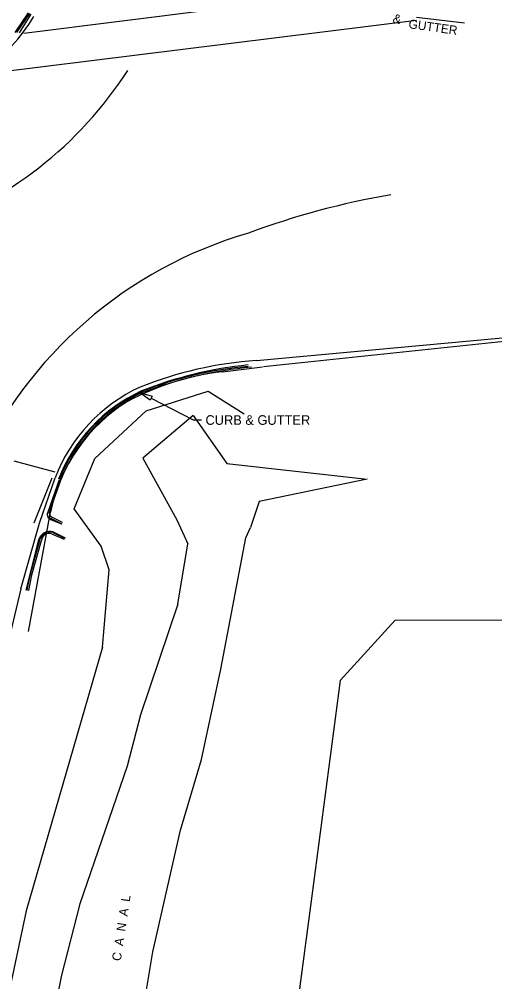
# Model space of a CAD drawing. Extents: x 925226 to 926411, y 852913 to 858733.
# Drawn here: x 925877.3 to 926026.1, y 857833.9 to 858134.9 of the extents above; entities that cross this region are included whole.
import ezdxf

# ---------------------------------------------------------------- set-up
doc = ezdxf.new("R2010")
doc.units = 0
for name, color, linetype in [('BankMent_ep', 7, 'Continuous'), ('CGep_ep', 7, 'Continuous'), ('CGFace_ep', 7, 'Continuous'), ('EndTreat_ep', 7, 'Continuous'), ('Fence_ep', 7, 'Continuous'), ('GuardrailRt_ep', 7, 'Continuous'), ('LaneLine_ep', 7, 'Continuous'), ('PavtAsphalt_ep', 7, 'Continuous'), ('TextLabel', 7, 'Continuous'), ('WaterEdge_ep', 7, 'Continuous'), ('XSPt_ep', 7, 'Continuous')]:
    doc.layers.add(name, color=color, linetype=linetype)

msp = doc.modelspace()

# ---------------------------------------------------------------- linework, layer by layer
at = {"layer": 'BankMent_ep'}
for p, q in [((925916.99, 858012.42), (925936.36, 858018.57)), ((925936.36, 858018.57), (925947.68, 858011.51)), ((925900.92, 857997.55), (925916.99, 858012.42)), ((925894.48, 857981.83), (925900.92, 857997.55)), ((925902.95, 857970.08), (925894.48, 857981.83)), ((925905.41, 857962.71), (925902.95, 857970.08)), ((925903.38, 857938.47), (925905.41, 857962.71)), ((925903.38, 857938.47), (925879.41, 857856.06)), ((925879.41, 857856.06), (925859.54, 857762.3))]:
    msp.add_line(p, q, dxfattribs=at)
at = {"layer": 'CGep_ep'}
for p, q in [((925880.88, 858136.47), (925877.28, 858130.67)), ((925887.16, 857978.4), (925886.13, 857979.3)), ((925890.66, 857976.98), (925887.16, 857978.4)), ((925879.41, 857956.31), (925883.44, 857972.21)), ((925887.93, 857974.56), (925891.68, 857972.76))]:
    msp.add_line(p, q, dxfattribs=at)
for centre, major_axis, ratio, start_param, end_param in [((925960.87, 857905.27), (-120.52, -23.58), 0.994162, 4.617452, 4.898036), ((925936.77, 857972.59), (-47.11, -18.8), 0.999852, 4.763609, 5.531038), ((925886.88, 857971.08), (-1.58, -3.27), 0.99725, 3.298139, 4.843297)]:
    msp.add_ellipse(centre, major_axis=major_axis, ratio=ratio, start_param=start_param, end_param=end_param, dxfattribs=at)
at = {"layer": 'CGFace_ep'}
for p, q in [((925880.51, 858136.71), (925876.45, 858130.76)), ((925886.32, 857980.87), (925889.83, 857990.97)), ((925890.67, 857977.02), (925887.12, 857978.76)), ((925880.68, 857961.08), (925883.8, 857972.26)), ((925887.75, 857974.35), (925891.44, 857972.66)), ((925879.73, 857956.42), (925880.68, 857961.08))]:
    msp.add_line(p, q, dxfattribs=at)
for centre, major_axis, ratio, start_param, end_param in [((925959.38, 857907.97), (-117.43, -23.12), 0.99279, 4.60691, 4.89159), ((925936.55, 857972.98), (-46.58, -18.35), 0.999879, 4.763057, 5.540256), ((925887.37, 857980.07), (-0.45, -1.26), 0.991381, 4.406439, 6.434016), ((925886.73, 857971.46), (-1.44, -2.71), 0.988346, 3.293296, 4.933222)]:
    msp.add_ellipse(centre, major_axis=major_axis, ratio=ratio, start_param=start_param, end_param=end_param, dxfattribs=at)
at = {"layer": 'EndTreat_ep'}
for p, q in [((925983.15, 858143.63), (925878.67, 858130.44)), ((926001.53, 858134.57), (925864.02, 858117.45)), ((925875.55, 857996.8), (925888.4, 857993.38))]:
    msp.add_line(p, q, dxfattribs=at)
for centre, major_axis, ratio, start_param, end_param in [((925807.98, 858185.37), (-64.65, -104.4), 0.999977, 0.878674, 1.553582), ((926034.63, 857838.21), (-162.69, 183.52), 0.999981, 5.726151, 5.914377), ((925986.75, 857938.13), (-47.22, 126.76), 0.999982, 6.209163, 7.073626)]:
    msp.add_ellipse(centre, major_axis=major_axis, ratio=ratio, start_param=start_param, end_param=end_param, dxfattribs=at)
at = {"layer": 'Fence_ep'}
for p, q in [((925994.86, 857946.96), (925977.68, 857928.14)), ((925994.86, 857946.96), (926067.01, 857947.19)), ((925977.68, 857928.14), (925968.87, 857860.74)), ((925968.87, 857860.74), (925946.09, 857691.45))]:
    msp.add_line(p, q, dxfattribs=at)
at = {"layer": 'GuardrailRt_ep'}
for p, q in [((926060.69, 858037.46), (925953.66, 858026.25)), ((925940.83, 858024.69), (925953.42, 858026.25)), ((925880.16, 857943.37), (925887.07, 857980.75))]:
    msp.add_line(p, q, dxfattribs=at)
for centre, major_axis, ratio, start_param, end_param in [((925950.63, 857941.9), (-81.73, -20.88), 0.988111, 4.581616, 4.9524), ((925939.58, 857969.93), (-46.9, -25.99), 0.999655, 4.765052, 5.573597)]:
    msp.add_ellipse(centre, major_axis=major_axis, ratio=ratio, start_param=start_param, end_param=end_param, dxfattribs=at)
at = {"layer": 'LaneLine_ep'}
msp.add_line((925887.46, 857991.42), (925881.89, 857977.33), dxfattribs=at)
at = {"layer": 'PavtAsphalt_ep'}
for p, q in [((926001.59, 858135.59), (926016.58, 858133.78)), ((925951.48, 858028.19), (926060.36, 858038.24)), ((925883.65, 857977.29), (925888.48, 857991.48)), ((925877.79, 857956.76), (925883.65, 857977.29)), ((925877.79, 857956.76), (925855.06, 857861.93))]:
    msp.add_line(p, q, dxfattribs=at)
for centre, major_axis, ratio, start_param, end_param in [((925840.63, 858159.33), (46.88, 7.33), 0.999985, 4.643805, 5.609384), ((925959.78, 857908.55), (-118.33, -22.67), 0.995366, 4.592866, 4.903832), ((925936.76, 857972.88), (-50.27, -12.23), 0.99992, 4.905666, 5.676813)]:
    msp.add_ellipse(centre, major_axis=major_axis, ratio=ratio, start_param=start_param, end_param=end_param, dxfattribs=at)
at = {"layer": 'TextLabel'}
msp.add_lwpolyline([(925918.21, 858015.8), (925914.95, 858018.21), (925918.82, 858016.99)], close=True, dxfattribs=at)
for points in [[(925918.51, 858016.4), (925931.73, 858009.66)], [(925931.73, 858009.66), (925934.26, 858009.66)]]:
    msp.add_lwpolyline(points, dxfattribs=at)
at = {"layer": 'WaterEdge_ep'}
for p, q in [((925931.71, 858011.03), (925915.99, 857997.59)), ((925931.71, 858011.03), (925942.28, 857996.02)), ((925915.99, 857997.59), (925926.59, 857978.4)), ((925942.28, 857996.02), (925986.14, 857991.11)), ((925986.14, 857991.11), (925952.39, 857984.08)), ((925952.39, 857984.08), (925949.6, 857975.97)), ((925926.59, 857978.4), (925930.05, 857970.85)), ((925948.13, 857972.69), (925949.6, 857975.97)), ((925940.33, 857931.66), (925948.13, 857972.69)), ((925926.94, 857951.98), (925930.05, 857970.85)), ((925926.94, 857951.98), (925915.17, 857917.4)), ((925934.31, 857903.36), (925940.33, 857931.66)), ((925915.17, 857917.4), (925911.05, 857901.27)), ((925927.77, 857881.27), (925934.31, 857903.36)), ((925911.05, 857901.27), (925896.21, 857858.27)), ((925919.04, 857843.24), (925927.77, 857881.27)), ((925896.21, 857858.27), (925890.51, 857835.92)), ((925915.14, 857819.77), (925919.04, 857843.24)), ((925890.51, 857835.92), (925886.52, 857815.79))]:
    msp.add_line(p, q, dxfattribs=at)
at = {"layer": 'XSPt_ep'}
for p, q in [((925880.04, 858136.89), (925875.92, 858130.82)), ((925886.96, 857981.41), (925890.4, 857991.1)), ((925890.86, 857977.47), (925887.44, 857979.15)), ((925887.42, 857973.99), (925891.36, 857972.26)), ((925881.2, 857961.19), (925884.21, 857971.86)), ((925880.26, 857956.23), (925881.2, 857961.19)), ((925879.73, 857956.42), (925879.41, 857956.31)), ((925880.26, 857956.23), (925879.73, 857956.42))]:
    msp.add_line(p, q, dxfattribs=at)
for centre, major_axis, ratio, start_param, end_param in [((925961.47, 857899.52), (-125.38, -25.91), 0.992736, 4.599832, 4.874706), ((925937.09, 857972.71), (-49.09, -10.45), 0.999917, 4.940147, 5.698181), ((925888.25, 857980.53), (-0.27, -1.59), 0.966095, 4.299236, 5.911055), ((925886.68, 857971.59), (-1.09, -2.26), 0.985238, 3.291446, 5.046515)]:
    msp.add_ellipse(centre, major_axis=major_axis, ratio=ratio, start_param=start_param, end_param=end_param, dxfattribs=at)

# ---------------------------------------------------------------- texts
at = {"layer": 'TextLabel'}
for s, height, rotation, p in [('&', 2.8, 346.2491, (925993.96, 858133.97)), ('GUTTER', 2.8, 351.9542, (925998.94, 858132.16)), ('CURB & GUTTER', 3, 360, (925935.55, 858008.07)), ('C  A  N  A  L', 2.8, 81.4783, (925909.04, 857840.21))]:
    msp.add_text(s, height=height, rotation=rotation, dxfattribs=at).set_placement(p)

doc.saveas('drawing.dxf')
